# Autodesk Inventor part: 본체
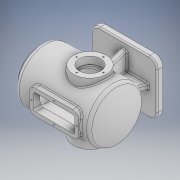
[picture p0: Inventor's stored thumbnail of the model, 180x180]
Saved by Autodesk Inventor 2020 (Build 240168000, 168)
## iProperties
Created: 2021-11
Part Number: 본체
Material: 일반
Document SubType Name: Modeling
Designer: Administrator
Density: 1 g/cm^3
Appearance: 기본값
Author: Administrator
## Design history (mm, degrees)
sketch "스케치1"
  geometry: L1 (-80, 65)-(80, 65); L2 (80, 65)-(80, -65); L3 (80, -65)-(-80, -65); L4 (-80, -65)-(-80, 65); L5 (-80, 65)-(80, -65); L6 (80, 65)-(-80, -65); 1 further point
  constraints: 12 end point, 2 midpoint, 2 parallel, 1 horizontal, 1 perpendicular
  dimensions: "d0" = 160 distance of L2.end L3.end; "d1" = 130 distance of L1.end L2.end
extrude "돌출1" new body sketch "스케치1" distance "d2" = 14; taper "d3" = 0 deg
sketch "스케치2"
  geometry: L1 (100, 179)-(-78.741, 179); L2 (-100, 114)-(110, 114); L3 (100, 179)-(100, 161.5); L4 (110, 146.5)-(85, 146.5); L5 (85, 146.5)-(85, 169); L6 (85, 169)-(-73.516, 169); L7 (0, 0)-(0, 222.03); L8 (100, 161.5)-(110, 161.5); L9 (110, 161.5)-(110, 114); L10 (80, 0)-(-80, 0) reference; L11 (80, 0)-(80, 14) reference; A1 r 110 centre (10, 114) between (-78.741, 179) and (-100, 114); A2 r 100 centre (10, 114) between (-73.516, 169) and (-90, 114); 1 further point
  constraints: 18 end point, 5 point on line, 4 point on circle, 3 horizontal, 2 centre point, 2 parallel, 2 perpendicular, 2 vertical
  dimensions: "d16" = 110 radius of A1; "d17" = 10 radial gap between concentric circles of A1 A2; "d24" = 210 distance from line of L2.start L9; "d25" = 114 distance between parallel lines of L10 L2; "d26" = 130 diameter of L1 L2; "d27" = 95 diameter of L8 L2; "d28" = 65 diameter of L4 L2; "d29" = 110 diameter of L6 L2; "d30" = 10 distance of L3.end L8.end; "d31" = 30 distance between parallel lines of L11 L9; "d32" = 25 distance of L4.start L4.end
revolve "회전1" stored, may be unused: angle "d18" = 90 deg
sketch "스케치5"
  geometry: L1 (-7, 7)-(7, 7); L2 (7, 7)-(7, -7); L3 (7, -7)-(-7, -7); L4 (-7, -7)-(-7, 7); L5 (-7, 7)-(7, -7); L6 (7, 7)-(-7, -7); 1 further point
  constraints: 12 end point, 2 midpoint, 2 parallel, 1 horizontal, 1 perpendicular
  dimensions: "d33" = 14 distance of L2.end L3.end; "d34" = 14 distance of L1.end L2.end
extrude "돌출2" join sketch "스케치5" stored distance "d35" = 14; taper "d36" = 0 deg
node "작업 평면2"
sketch "스케치7"
  geometry: L1 (-60, 30)-(60, 30); L2 (60, 30)-(60, -30); L3 (60, -30)-(-60, -30); L4 (-60, -30)-(-60, 30); L5 (-110, 47.5)-(-110, -47.5) reference; 2 further points
  constraints: 8 end point, 2 parallel, 1 horizontal, 1 horizontal alignment, 1 midpoint, 1 perpendicular
  dimensions: "d40" = 50 distance between parallel lines of L4 L5; "d41" = 120 distance of L1.start L1.end; "d42" = 60 distance of L1.end L2.end
extrude "돌출3" join sketch "스케치7" stored distance "d43" = 14; taper "d44" = 0 deg
sketch "스케치8"
  geometry: L1 (60, 30)-(-60, 30) reference; L2 (-60, 30)-(-60, -30) reference; L3 (-60, -30)-(60, -30) reference; L4 (60, -30)-(60, 30) reference; L5 (-50, 20)-(50, 20); L6 (50, 20)-(50, -20); L7 (50, -20)-(-50, -20); L8 (-50, -20)-(-50, 20); 1 further point
  constraints: 8 end point, 3 other
  dimensions: "d45" = 10 distance between parallel lines of L1 L5
extrude "돌출4" cut sketch "스케치8" stored distance "d46" = 14; taper "d47" = 0 deg
sketch "스케치9"
  geometry: L1 (10, 114)-(186.233, 114); L2 (186.233, 114)-(-208.049, 114); L3 (-17, 234.122)-(-17, -84.071); L4 (110, 66.5)-(110, 161.5) reference; C1 r 40 at (-17, 114); A1 r 110 centre (10, 114) between (-78.741, 179) and (-78.741, 49) reference; 2 further points
  constraints: 6 end point, 3 point on line, 1 centre point, 1 coincident, 1 horizontal, 1 vertical
  dimensions: "d48" = 127 distance between parallel lines of L3 L4; "d49" = 80 diameter of C1
extrude "돌출5" join sketch "스케치9" stored distance "d50" = 150; taper "d51" = 0 deg
sketch "스케치11"
  geometry: C1 r 40 at (0, 0) reference; C2 r 26 at (0, 0); 1 further point
  constraints: 1 centre point, 1 coincident
  dimensions: "d52" = 52 diameter of C2
extrude "돌출6" cut sketch "스케치11" distance "d53" = 18; taper "d54" = 0 deg
sketch "스케치12"
  geometry: C1 r 40 at (-17, 114) reference; C2 r 21 at (-17, 114); 1 further point
  constraints: 1 centre point, 1 coincident
  dimensions: "d55" = 42 diameter of C2
extrude "돌출7" cut sketch "스케치12" stored distance "d56" = 18; taper "d57" = 0 deg
fillet "모깎기1" dims "d58" = 0.3
sketch "스케치13"
  geometry: L1 (-39.739, 42.191)-(-50, 14); L2 (-65, 0)-(65, 0) reference; L3 (-65, 14)-(65, 14) reference; 2 further points
  constraints: 2 end point, 1 coincident, 1 point on line
  dimensions: "d59" = 110 deg angle of L2 L1; "d60" = 50 horizontal distance of L1.end point (0, 0); "d61" = 30 distance of L1.start L1.end
feature "리브1" sketch "스케치13" dims "d62" = 1, "d63" = 14, "d64" = 0, "d65" = 0, "d66" = 1, "d67" = 1
sketch "스케치14"
  geometry: L1 (49.739, 42.191)-(60, 14); L2 (80, 14)-(-80, 14) reference; 2 further points
  constraints: 2 end point, 1 coincident, 1 point on line
  dimensions: "d68" = 60 horizontal distance of L1.end point (0, 0); "d69" = 110 deg angle of L2 L1; "d71" = 30 distance of L1.start L1.end
feature "리브2" sketch "스케치14" dims "d72" = 1, "d73" = 14, "d74" = 0, "d75" = 0, "d76" = 1, "d77" = 1
fillet "모깎기2" dims "d78" = 10
fillet "모깎기3" dims "d79" = 10
fillet "모깎기4" dims "d80" = 20
fillet "모깎기5" dims "d81" = 15
fillet "모깎기6" dims "d82" = 5
fillet "모깎기7" dims "d83" = 3
fillet "모깎기8" dims "d84" = 3
fillet "모깎기9" dims "d85" = 3
fillet "모깎기10" dims "d86" = 3
node "작업 평면3"
sketch "스케치16"
  geometry: L1 (-20.739, 8.002)-(20.739, 8.002); L2 (20.739, 8.002)-(20.739, 1.998); L3 (20.739, 1.998)-(-20.739, 1.998); L4 (-20.739, 1.998)-(-20.739, 8.002); L5 (-20.739, 8.002)-(20.739, 1.998); L6 (20.739, 8.002)-(-20.739, 1.998); L7 (-60, 0)-(60, 0) reference; L8 (-80, 11)-(-80, 0) reference; 4 further points
  constraints: 4 end point, 3 midpoint, 1 vertical alignment, 2 other
  dimensions: "d88" = 5 distance from line of L7 point (0, 5); "d89" = 8.00204 distance between parallel lines of L7 L1; "d90" = 59.26052 distance between parallel lines of L8 L4
feature "엠보싱1" sketch "스케치16" dims "d16" = 110, "d17" = 10, "d24" = 210, "d25" = 114, "d26" = 130, "d27" = 95, "d28" = 65, "d29" = 110, "d30" = 10, "d31" = 30, "d32" = 25, "d91" = 0.5, "d92" = 0
sketch "스케치17" dims "d93" = 80
  geometry: L1 (0, 0)-(97.424, 0); C1 r 47.5 at (0, 0) reference; C2 r 32.5 at (0, 0) reference; 2 further points
  constraints: 2 end point, 1 coincident, 1 horizontal, 1 horizontal alignment, 1 point on line, 2 other
hole "구멍1" sketch "스케치17" at (40, 0) diameter "d94" = 3.242; stored, may be unused: countersink angle "d98" = 90 deg, drill point angle "d100" = 118 deg; dims "d95" = 11, "d96" = 4, "d97" = 2, "d99" = 13
sketch "스케치18" dims "d104" = 65
  geometry: L1 (0, 0)-(0, 85.407); C1 r 40 at (0, 0) reference; C2 r 26 at (0, 0) reference; 2 further points
  constraints: 2 end point, 1 coincident, 1 point on line, 1 vertical, 1 vertical alignment, 2 other
hole "구멍2" sketch "스케치18" at (0, 32.5) diameter "d105" = 3.242; stored, may be unused: countersink angle "d109" = 90 deg, drill point angle "d111" = 118 deg; dims "d106" = 11, "d107" = 4, "d108" = 2, "d110" = 13
revolve "회전2" stored, may be unused: angle "d115" = 90 deg
sketch "스케치19"
  geometry: L1 (0, -86.329)-(0, 146.225); L2 (-121.798, 0)-(129.16, 0); 5 further points
  constraints: 6 point on line, 4 end point, 1 horizontal, 1 vertical
  dimensions: "d116" = 55 distance of point (0, 0) point (-55, 0); "d117" = 55 distance from line of L1 point (55, 0); "d118" = 25 distance of point (0, 0) point (0, -25); "d119" = 25 distance of point (0, 0) point (0, 25)
hole "구멍3" sketch "스케치19" at (-55, 0), (0, -25), (55, 0), (0, 25) diameter "d120" = 3.242; stored, may be unused: countersink angle "d124" = 90 deg, drill point angle "d126" = 118 deg; dims "d121" = 9, "d122" = 4, "d123" = 2, "d125" = 11
node "솔리드1"
mirror "미러1"
mirror "미러2"
mirror "미러3"
pattern_circular "원형 패턴1" dims angle "d102" = 360 deg
pattern_circular "원형 패턴2" dims angle "d113" = 360 deg
mirror "미러4"
node "투영된 루프1"
node "투영된 루프3"
node "투영된 루프4"
node "투영된 루프5"
node "투영된 루프6"
feature "A9D066F2-1C7D-4E18-AEED-F7BC21143FA4" dims "d105" = 3.242, "d106" = 11, "d107" = 4, "d108" = 2, "d109" = 90 deg, "d110" = 13, "d111" = 118 deg
other parameters: "d39" = 184, "d87" = -116.5
